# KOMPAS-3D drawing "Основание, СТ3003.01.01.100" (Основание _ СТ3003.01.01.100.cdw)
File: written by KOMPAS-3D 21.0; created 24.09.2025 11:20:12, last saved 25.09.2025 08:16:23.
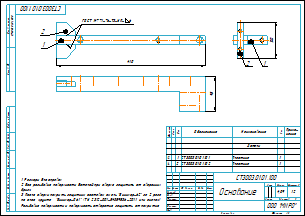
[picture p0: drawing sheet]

Sheet 1: A3, landscape

Document properties: Полное имя файла: ..\..\..\3D\Кронштейн _ СТ3003.01.01.000\Основание _ СТ3003.01.01.100\Основание _ СТ3003.01.01.100.a3d; Масса: 4.086618

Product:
- Part/product: Основание  | designation СТ3003.01.01.100
    Масса: 4.086618
    Форматы листов документа: A3
  - Component [detail]: Пластина  | designation СТ3003.01.01.101  | pos. 1  | Материал: Лист$dБ-ПН-НО-25 ГОСТ 19903-2015;Ст3сп ГОСТ 14637-89$ (density 7850 kg/m3); Масса: 3.643787; Форматы листов документа: A2; source file: ..\..\..\3D\Кронштейн _ СТ3003.01.01.000\Основание _ СТ3003.01.01.100\Пластина _ СТ3003.01.01.101.m3d, Пластина _ СТ3003.01.01.101.cdw
  - Component [detail]: Пластина  | designation СТ3003.01.01.102  | pos. 2  | Материал: Лист$dБ-ПН-НО-16 ГОСТ 19903-2015;Ст3сп ГОСТ 14637-89$ (density 7850 kg/m3); Масса: 0.442831; Форматы листов документа: A4; source file: ..\..\..\3D\Кронштейн _ СТ3003.01.01.000\Основание _ СТ3003.01.01.100\Пластина _ СТ3003.01.01.102.m3d, Пластина _ СТ3003.01.01.102.cdw

Title block, sheet 1: Наименование: Основание; designation: СТ3003.01.01.100; Масса: 4,09; Количество листов документа: 1; organisation: ООО "МИРО"; Форматы листов документа: A3; stored path: C:\Users\1\Yandex.Disk\Документы\Новая папка\Стапель №2\Стапель _ СТ3003.00.00.000\Опора _ СТ3003.01.00.000\2D\Кронштейн _ СТ3003.01.01.000\Основание _ СТ3003.01.01.100\Основание _ СТ3003.01.01.100.cdw

Views: Вид 1, Спереди
Referenced files in C:\Users\1\Yandex.Disk\Документы\Новая папка\Стапель №2\Стапель _ СТ3003.00.00.000\Опора _ СТ3003.01.00.000\3D\Кронштейн _ СТ3003.01.01.000\Основание _ СТ3003.01.01.100\: Основание _ СТ3003.01.01.100.a3d, Пластина _ СТ3003.01.01.102.m3d, Пластина _ СТ3003.01.01.101.m3d
Referenced files in C:\Users\1\Yandex.Disk\Документы\Новая папка\Стапель №2\Стапель _ СТ3003.00.00.000\Опора _ СТ3003.01.00.000\2D\Кронштейн _ СТ3003.01.01.000\Основание _ СТ3003.01.01.100\: Пластина _ СТ3003.01.01.102.cdw, Пластина _ СТ3003.01.01.101.cdw
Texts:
  ГОСТ 14771-76-Т3-УП- 6
  СТ3003.01.01.102
  Пластина
  СТ3003.01.01.101
  СТ3003.01.01.000
  СТ3003.01.01.101 Пластина
  СТ3003.01.01.102 Пластина
  СТ3003.01.01.100 Основание
Dimensions and other numbers on the sheet: 2; 1; 410; 0; 1:2; 4,09

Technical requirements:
  Размеры для справок.
  Все резьбовые поверхности деталей при сварке защитить от сварочных
  брызг.
  После сварки покрыть защитным составом эмаль "Виникор-62" за 2 раза
  по слою грунта  "Виникор-061" (ТУ 2312-001-54359536-2011 или аналог).
  Резьбовые поверхности и поверхность отверстия защитить от покрытия.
